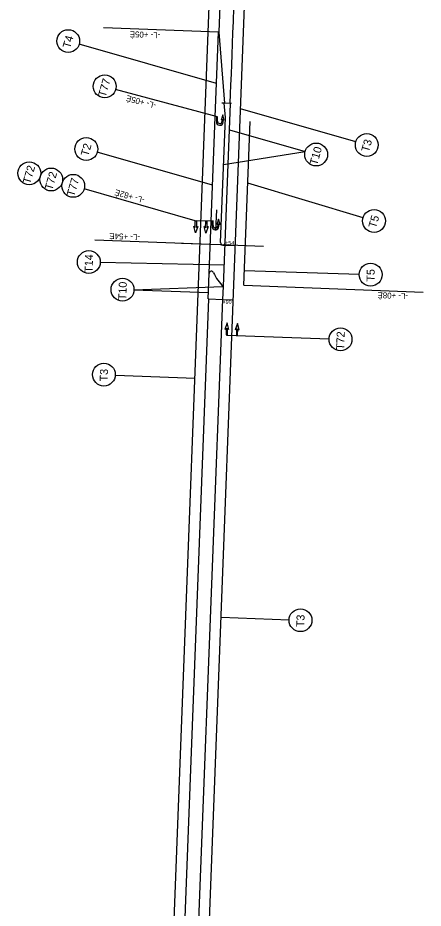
# Model space of a CAD drawing. Extents: x 1657109 to 2100937, y 684916 to 883211.
# Drawn here: x 2097532 to 2098010, y 687289 to 688340 of the extents above; entities that cross this region are included whole.
import ezdxf

# ---------------------------------------------------------------- set-up
doc = ezdxf.new("R2010")
doc.units = 0
for name, color, linetype in [('Prop CMT Pvmt Course 1', 7, 'Continuous'), ('Prop CMT Pvmt Gravel', 7, 'Continuous'), ('Prop Conc 1ft 6in Curb and Gutter', 7, 'Continuous'), ('Prop Conc 2ft 6in Curb and Gutter', 7, 'Continuous'), ('Prop Conc Curb 8in x 18in', 7, 'Continuous'), ('Prop Conc Curb and Gutter', 7, 'Continuous'), ('Prop Dimension', 7, 'Continuous'), ('Prop EOT', 7, 'Continuous'), ('Prop Lane Arrow CELL', 7, 'Continuous'), ('Prop VPT Ditch Grade Right Label', 7, 'Continuous'), ('Scratch_Level_5', 7, 'Continuous'), ('Scratch_Level_7', 7, 'Continuous')]:
    doc.layers.add(name, color=color, linetype=linetype)

msp = doc.modelspace()

# ---------------------------------------------------------------- linework, layer by layer
at = {"layer": 'Prop CMT Pvmt Course 1'}
for p, q in [((2097766.4, 688223.4), (2097766.2, 688217.4)), ((2097767.6, 688223.4), (2097766.4, 688223.4)), ((2097767.4, 688218.2), (2097767.6, 688223.4)), ((2097773.9, 688225.6), (2097771.8, 688219.5)), ((2097775.6, 688219.4), (2097773.9, 688225.6)), ((2097769.9, 688213.4), (2097770.3, 688213.4)), ((2097771.8, 688219.5), (2097773.1, 688220.7)), ((2097773.1, 688220.7), (2097773, 688218.1)), ((2097774.2, 688217.1), (2097774.3, 688220.6)), ((2097774.3, 688220.6), (2097775.6, 688219.4)), ((2097761.3, 688100.1), (2097761.2, 688094)), ((2097762.5, 688100), (2097761.3, 688100.1)), ((2097762.4, 688094.9), (2097762.5, 688100)), ((2097768.8, 688102.3), (2097766.7, 688096.2)), ((2097766.7, 688096.2), (2097768.1, 688097.4)), ((2097768.1, 688097.4), (2097768, 688094.8)), ((2097770.5, 688096.1), (2097768.8, 688102.3)), ((2097769.2, 688093.8), (2097769.3, 688097.3)), ((2097769.3, 688097.3), (2097770.5, 688096.1)), ((2097764.9, 688090.1), (2097765.3, 688090.1))]:
    msp.add_line(p, q, dxfattribs=at)
for centre, radius, start, end in [((2097770, 688217.3), 3.82, 178.3671, 268.3671), ((2097770.2, 688218.2), 2.81, 178.3671, 268.3671), ((2097770.2, 688218.2), 2.81, 268.3671, 358.3671), ((2097770.4, 688217.2), 3.82, 268.3671, 358.3671), ((2097765, 688093.9), 3.82, 178.3671, 268.3671), ((2097765.2, 688094.8), 2.81, 178.3671, 268.3671), ((2097765.2, 688094.8), 2.81, 268.3671, 358.3671), ((2097765.4, 688093.9), 3.82, 268.3671, 358.3671)]:
    msp.add_arc(centre, radius, start, end, dxfattribs=at)
at = {"layer": 'Prop CMT Pvmt Gravel'}
for p, q in [((2097768.6, 688323.1), (2097633, 688328.3)), ((2097766.3, 688262.6), (2097604.3, 688308.9)), ((2097767.6, 688223.4), (2097647.3, 688255.5)), ((2097930.8, 688193.8), (2097794.7, 688232.8)), ((2097781.7, 688208.1), (2097871, 688182.5)), ((2097761.7, 688142.6), (2097625.6, 688181.5)), ((2097774.6, 688167.1), (2097871, 688182.5)), ((2097939.4, 688104.1), (2097803.3, 688145.1)), ((2097741.3, 688100.6), (2097610.2, 688138.1)), ((2097762.8, 688100), (2097742.4, 688100.6)), ((2097759, 688072.5), (2097622.9, 688077.7)), ((2097773.7, 688071.9), (2097787.5, 688071.3)), ((2097775.6, 688048.3), (2097629.1, 688051.3)), ((2097934.8, 688037.2), (2097799.3, 688041.5)), ((2097798.7, 688024.5), (2098010.4, 688016.4)), ((2097773.9, 688022.7), (2097668.9, 688018.8)), ((2097756.8, 688015.4), (2097668.9, 688018.8)), ((2097774, 688007.6), (2097785, 688007.2)), ((2097778.5, 687965.7), (2097899.3, 687961.1)), ((2097647.2, 687918.5), (2097741, 687914.9)), ((2097771.7, 687632.6), (2097852, 687629.5))]:
    msp.add_line(p, q, dxfattribs=at)
for centre in [(2097591.3, 688312.7), (2097634.4, 688259.3), (2097943.8, 688190.1), (2097612.6, 688185.3), (2097884, 688178.8), (2097545.3, 688156.7), (2097571.2, 688149.3), (2097597.2, 688141.8), (2097952.4, 688100.4), (2097615.6, 688051.8), (2097948.3, 688037), (2097655.4, 688019.3), (2097912.8, 687960.6), (2097633.4, 687919), (2097865.5, 687629)]:
    msp.add_circle(centre, 13.5, dxfattribs=at)
at = {"layer": 'Prop Conc 1ft 6in Curb and Gutter'}
msp.add_line((2097757.7, 688038.3), (2097764.8, 688223.1), dxfattribs=at)
at = {"layer": 'Prop Conc 2ft 6in Curb and Gutter'}
msp.add_line((2097764.8, 688223.1), (2097768.6, 688323.1), dxfattribs=at)
at = {"layer": 'Prop Conc Curb 8in x 18in'}
for points in [[(2097783.9, 688239.1), (2097775.8, 688239.4), (2097772.8, 688239.6)], [(2097822, 688070.1), (2097771, 688072), (2097724.9, 688073.8)]]:
    msp.add_lwpolyline(points, dxfattribs=at)
at = {"layer": 'Prop Conc Curb and Gutter'}
for p, q in [((2097776.8, 688222.7), (2097775.4, 688239.5)), ((2097776.6, 688074.6), (2097782.9, 688239.2)), ((2097771.1, 688074.8), (2097776.8, 688222.7)), ((2097756.5, 688008.3), (2097757.7, 688038.3)), ((2097774, 688007.6), (2097774.6, 688023))]:
    msp.add_line(p, q, dxfattribs=at)
for centre, radius, start, end in [((2097773.9, 688074.7), 2.75, 177.8037, 357.8037), ((2097760.4, 688038.2), 2.75, 23.7977, 177.8037), ((2097808, 688059.2), 49.3, 203.7977, 227.297)]:
    msp.add_arc(centre, radius, start, end, dxfattribs=at)
at = {"layer": 'Prop Dimension'}
msp.add_line((2097765.6, 688089), (2097766.6, 688113.4), dxfattribs=at)
at = {"layer": 'Prop EOT'}
for p, q in [((2097705.9, 687000.5), (2097764.5, 688529.2)), ((2097747.4, 686998.9), (2097806, 688527.6))]:
    msp.add_line(p, q, dxfattribs=at)
at = {"layer": 'Prop Lane Arrow CELL'}
msp.add_line((2097798.7, 688024.5), (2097806.1, 688217.8), dxfattribs=at)
at = {"layer": 'Prop VPT Ditch Grade Right Label'}
msp.add_line((2097774.6, 688023), (2097776.6, 688074.6), dxfattribs=at)
at = {"layer": 'Scratch_Level_5'}
for points in [[(2097739.5, 688094.2), (2097741.1, 688092.6), (2097741.3, 688100.6), (2097742.8, 688100.6), (2097742.6, 688092.6), (2097744.2, 688094), (2097741.6, 688086.5)], [(2097739.5, 688094.2), (2097741.1, 688092.6), (2097741.3, 688100.6), (2097742.8, 688100.6), (2097742.6, 688092.6), (2097744.2, 688094), (2097741.6, 688086.5)], [(2097751.8, 688093.8), (2097753.4, 688092.3), (2097753.6, 688100.3), (2097755.1, 688100.2), (2097754.9, 688092.2), (2097756.5, 688093.7), (2097753.9, 688086.1)], [(2097751.8, 688093.8), (2097753.4, 688092.3), (2097753.6, 688100.3), (2097755.1, 688100.2), (2097754.9, 688092.2), (2097756.5, 688093.7), (2097753.9, 688086.1)], [(2097776.3, 687972.3), (2097777.9, 687973.8), (2097777.7, 687965.8), (2097779.2, 687965.7), (2097779.4, 687973.7), (2097781, 687972.2), (2097778.9, 687979.9)], [(2097776.3, 687972.3), (2097777.9, 687973.8), (2097777.7, 687965.8), (2097779.2, 687965.7), (2097779.4, 687973.7), (2097781, 687972.2), (2097778.9, 687979.9)], [(2097788.4, 687971.8), (2097790, 687973.3), (2097789.8, 687965.3), (2097791.3, 687965.3), (2097791.5, 687973.2), (2097793.1, 687971.7), (2097791, 687979.4)], [(2097788.4, 687971.8), (2097790, 687973.3), (2097789.8, 687965.3), (2097791.3, 687965.3), (2097791.5, 687973.2), (2097793.1, 687971.7), (2097791, 687979.4)]]:
    msp.add_lwpolyline(points, close=True, dxfattribs=at)
at = {"layer": 'Scratch_Level_7'}
msp.add_lwpolyline([(2097786.5, 688352.5), (2097785.9, 688336), (2097785.4, 688322.5), (2097784.9, 688309.9), (2097784.4, 688296.3), (2097783.9, 688285), (2097783.5, 688273.9), (2097783, 688260.8), (2097782.6, 688250.6), (2097782.2, 688239.2), (2097776.2, 688239.4), (2097769.4, 688323.1), (2097777.3, 688528.7)], dxfattribs=at)
msp.add_lwpolyline([(2097715.8, 686919), (2097718.6, 687000), (2097757.3, 688008.3), (2097773.3, 688007.7), (2097734.6, 686999.4), (2097731.8, 686918.5)], close=True, dxfattribs=at)

# ---------------------------------------------------------------- texts
at = {"layer": 'Prop CMT Pvmt Gravel'}
for s, height, rotation, p in [('T4', 9.45, 74.0259, (2097593.6, 688303.5)), ('-L- +05È', 7, 177.8037, (2097700.2, 688323)), ('T77', 9.45, 74.0259, (2097635.4, 688245.9)), ('-L- +05È', 7, 164.8652, (2097695.7, 688239.6)), ('T2', 9.45, 74.0259, (2097614.9, 688176.1)), ('T3', 9.45, 74.0259, (2097946.1, 688181)), ('T10', 9.45, 74.0259, (2097885.1, 688165.5)), ('T72', 9.45, 74.0259, (2097546.4, 688143.4)), ('T72', 9.45, 74.0259, (2097572.3, 688136)), ('T77', 9.45, 74.0259, (2097598.3, 688128.5)), ('-L- +82È', 7, 163.9486, (2097682.1, 688127.8)), ('T5', 9.45, 74.0259, (2097954.6, 688091.3)), ('-L- +54È', 7, 177.8037, (2097676.1, 688084.7)), ('+54', 4.5, 357.3716, (2097776.6, 688072.5)), ('T14', 9.45, 87.8037, (2097619.9, 688039.1)), ('T5', 9.45, 88.9252, (2097952.9, 688028.7)), ('T10', 9.45, 87.8037, (2097659.7, 688006.7)), ('-L- +08È', 7, 177.8037, (2097992.7, 688014.9)), ('+90', 4.5, 359.5147, (2097773.6, 688002.5)), ('T72', 9.45, 87.8037, (2097917, 687948)), ('T3', 9.45, 87.8037, (2097637.8, 687910.8)), ('T3', 9.45, 87.8037, (2097869.9, 687620.7))]:
    msp.add_text(s, height=height, rotation=rotation, dxfattribs=at).set_placement(p)

doc.saveas('drawing.dxf')
